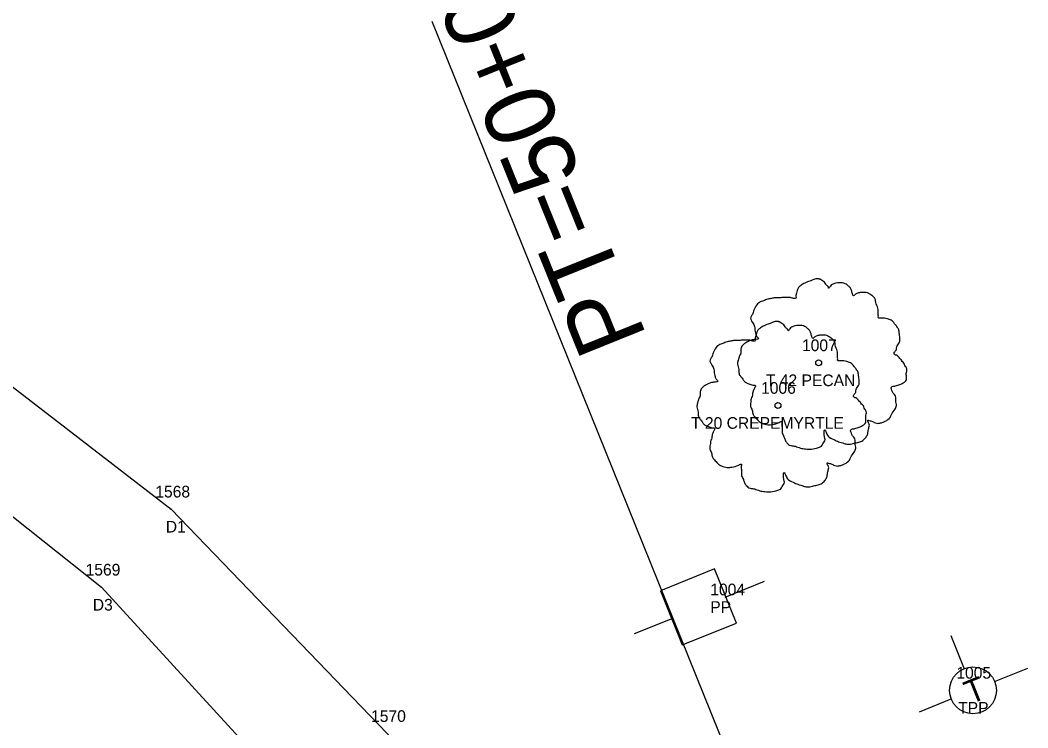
# Model space of a CAD drawing. Extents: x 1964982 to 1970452, y 1116335 to 1119906.
# Drawn here: x 1966698.6 to 1966784.8, y 1117479 to 1117539.6 of the extents above; entities that cross this region are included whole.
import ezdxf

# ---------------------------------------------------------------- set-up
doc = ezdxf.new("R2010")
doc.units = 0
for name, color, linetype in [('RD_EX_Driveway', 7, 'Continuous'), ('RD_EX_Driveway_txCode', 7, 'Continuous'), ('RD_EX_UT', 7, 'Continuous'), ('RD_EX_UT_txCode', 7, 'Continuous'), ('RD_EX_VEG', 7, 'Continuous'), ('RD_EX_VEG_txCode', 7, 'Continuous'), ('RD_HC_Data', 7, 'Continuous'), ('RD_SMD_Locator', 7, 'Continuous')]:
    doc.layers.add(name, color=color, linetype=linetype)

msp = doc.modelspace()

# ---------------------------------------------------------------- linework, layer by layer
at = {"layer": 'RD_EX_Driveway'}
for points in [[(1966578.028, 1117435.239), (1966571.581, 1117480.753), (1966567.97, 1117515.311), (1966576.556, 1117516.6), (1966582.112, 1117483.547), (1966603.624, 1117509.102), (1966634.749, 1117528.345), (1966662.085, 1117526.43), (1966689.524, 1117514.663), (1966711.523, 1117497.722), (1966730.008, 1117478.512), (1966744.031, 1117462.693), (1966734.107, 1117458.19)], [(1966589.3, 1117436.331), (1966587.977, 1117456.65), (1966594.083, 1117483.042), (1966609.697, 1117504.074), (1966638.325, 1117518.314), (1966661.317, 1117517.134), (1966685.434, 1117507.038), (1966705.558, 1117491.043), (1966722.871, 1117472.119), (1966734.107, 1117458.19)]]:
    msp.add_lwpolyline(points, dxfattribs=at)
at = {"layer": 'RD_EX_UT'}
for p, q in [((1966758.019, 1117492.607), (1966753.383, 1117490.734)), ((1966759.892, 1117487.971), (1966758.019, 1117492.607)), ((1966758.913, 1117490.204), (1966762.288, 1117491.568)), ((1966753.383, 1117490.734), (1966755.256, 1117486.098)), ((1966751.162, 1117487.073), (1966754.378, 1117488.373)), ((1966755.256, 1117486.098), (1966759.892, 1117487.971)), ((1966778.236, 1117486.915), (1966779.386, 1117484.069)), ((1966781.983, 1117482.978), (1966784.83, 1117484.128)), ((1966775.557, 1117480.382), (1966778.275, 1117481.48))]:
    msp.add_line(p, q, dxfattribs=at)
msp.add_circle((1966780.135, 1117482.215), 2, dxfattribs=at)
at = {"layer": 'RD_EX_VEG'}
for centre, radius in [((1966766.925, 1117510.253), 0.25), ((1966766.913, 1117510.234), 0.0001), ((1966763.446, 1117506.601), 0.25), ((1966763.434, 1117506.582), 0.0001)]:
    msp.add_circle(centre, radius, dxfattribs=at)
for points in [[(1966767.057, 1117517.42), (1966766.757, 1117517.445), (1966766.432, 1117517.345), (1966766.183, 1117517.245), (1966765.958, 1117517.17), (1966765.733, 1117517.07), (1966765.433, 1117516.896), (1966765.208, 1117516.696), (1966765.083, 1117516.446), (1966765.033, 1117516.221), (1966764.983, 1117515.946), (1966764.983, 1117515.771), (1966764.858, 1117515.746), (1966764.708, 1117515.771), (1966764.458, 1117515.846), (1966764.208, 1117515.846), (1966763.958, 1117515.846), (1966763.609, 1117515.821), (1966763.259, 1117515.821), (1966762.984, 1117515.771), (1966762.659, 1117515.721), (1966762.284, 1117515.596), (1966761.934, 1117515.471), (1966761.635, 1117515.221), (1966761.385, 1117514.747), (1966761.26, 1117514.397), (1966761.11, 1117514.147), (1966761.26, 1117513.697), (1966761.435, 1117513.347), (1966761.46, 1117513.147), (1966761.535, 1117512.722), (1966761.635, 1117512.498), (1966761.759, 1117512.298), (1966761.685, 1117512.273), (1966761.31, 1117512.223), (1966761.01, 1117512.123), (1966760.585, 1117511.898), (1966760.36, 1117511.673), (1966760.26, 1117511.348), (1966760.235, 1117510.998), (1966760.135, 1117510.798), (1966760.06, 1117510.523), (1966760.035, 1117510.448), (1966759.985, 1117510.124), (1966760.085, 1117509.674), (1966760.11, 1117509.324), (1966760.235, 1117509.099), (1966760.385, 1117508.924), (1966760.56, 1117508.674), (1966760.96, 1117508.449), (1966761.285, 1117508.349), (1966761.485, 1117508.324), (1966761.31, 1117507.825), (1966761.26, 1117507.475), (1966761.135, 1117507.075), (1966761.135, 1117507), (1966761.085, 1117506.525), (1966761.235, 1117506.2), (1966761.31, 1117505.825), (1966761.485, 1117505.601), (1966761.759, 1117505.301), (1966762.084, 1117505.076), (1966762.584, 1117504.951), (1966762.984, 1117504.976), (1966763.559, 1117505.151), (1966763.809, 1117505.226), (1966763.784, 1117505.051), (1966763.809, 1117504.676), (1966763.809, 1117504.251), (1966763.958, 1117503.926), (1966764.058, 1117503.651), (1966764.208, 1117503.401), (1966764.533, 1117503.177), (1966764.933, 1117503.102), (1966765.358, 1117502.952), (1966765.808, 1117502.877), (1966766.307, 1117502.852), (1966766.907, 1117503.002), (1966767.182, 1117503.127), (1966767.282, 1117503.302), (1966767.482, 1117503.676), (1966767.432, 1117503.901), (1966767.457, 1117504.501), (1966767.557, 1117504.326), (1966767.732, 1117503.976), (1966768.232, 1117503.676), (1966768.631, 1117503.501), (1966769.106, 1117503.351), (1966769.406, 1117503.277), (1966769.881, 1117503.351), (1966770.256, 1117503.426), (1966770.631, 1117503.551), (1966770.93, 1117503.826), (1966771.105, 1117504.101), (1966771.155, 1117504.376), (1966771.23, 1117504.751), (1966771.28, 1117504.926)], [(1966771.28, 1117504.926), (1966771.205, 1117505.101), (1966771.155, 1117505.351), (1966771.23, 1117505.326), (1966771.405, 1117505.276), (1966771.68, 1117505.151), (1966771.905, 1117505.076), (1966772.23, 1117505.101), (1966772.505, 1117505.201), (1966772.955, 1117505.476), (1966773.229, 1117505.95), (1966773.504, 1117506.35), (1966773.579, 1117506.675), (1966773.529, 1117506.9), (1966773.504, 1117507.4), (1966773.304, 1117507.65), (1966773.254, 1117507.775), (1966773.154, 1117508.174), (1966773.229, 1117508.224), (1966773.504, 1117508.274), (1966773.879, 1117508.399), (1966774.154, 1117508.524), (1966774.379, 1117508.699), (1966774.454, 1117508.924), (1966774.429, 1117509.324), (1966774.479, 1117509.724), (1966774.404, 1117509.874), (1966774.304, 1117510.024), (1966774.229, 1117510.224), (1966774.079, 1117510.373), (1966773.979, 1117510.523), (1966773.879, 1117510.623), (1966773.754, 1117510.773), (1966773.579, 1117510.898), (1966773.429, 1117510.948), (1966773.379, 1117511.098), (1966773.529, 1117511.298), (1966773.579, 1117511.398), (1966773.604, 1117511.623), (1966773.829, 1117511.973), (1966773.879, 1117512.373), (1966773.829, 1117512.797), (1966773.779, 1117513.072), (1966773.629, 1117513.347), (1966773.429, 1117513.597), (1966773.304, 1117513.772), (1966773.129, 1117513.897), (1966772.805, 1117514.022), (1966772.555, 1117514.072), (1966772.205, 1117514.072), (1966772.005, 1117514.122), (1966772.03, 1117514.172), (1966772.03, 1117514.322), (1966772.03, 1117514.597), (1966771.955, 1117515.046), (1966771.805, 1117515.546), (1966771.805, 1117515.571), (1966771.705, 1117515.821), (1966771.48, 1117516.021), (1966771.305, 1117516.121), (1966771.105, 1117516.246), (1966770.855, 1117516.271), (1966770.556, 1117516.271), (1966770.281, 1117516.221), (1966770.081, 1117516.121), (1966769.906, 1117515.996), (1966769.831, 1117516.146), (1966769.731, 1117516.446), (1966769.681, 1117516.596), (1966769.531, 1117516.771), (1966769.306, 1117516.971), (1966768.856, 1117517.095), (1966768.232, 1117517.021), (1966767.932, 1117516.821), (1966767.782, 1117516.646), (1966767.732, 1117516.771), (1966767.532, 1117516.971), (1966767.432, 1117517.145), (1966767.257, 1117517.27), (1966767.107, 1117517.37), (1966767.007, 1117517.42)], [(1966763.578, 1117513.768), (1966763.278, 1117513.793), (1966762.954, 1117513.693), (1966762.704, 1117513.594), (1966762.479, 1117513.519), (1966762.254, 1117513.419), (1966761.954, 1117513.244), (1966761.729, 1117513.044), (1966761.604, 1117512.794), (1966761.554, 1117512.569), (1966761.504, 1117512.294), (1966761.504, 1117512.119), (1966761.379, 1117512.094), (1966761.229, 1117512.119), (1966760.979, 1117512.194), (1966760.73, 1117512.194), (1966760.48, 1117512.194), (1966760.13, 1117512.169), (1966759.78, 1117512.169), (1966759.505, 1117512.119), (1966759.18, 1117512.069), (1966758.805, 1117511.944), (1966758.456, 1117511.819), (1966758.156, 1117511.569), (1966757.906, 1117511.095), (1966757.781, 1117510.745), (1966757.631, 1117510.495), (1966757.781, 1117510.045), (1966757.956, 1117509.695), (1966757.981, 1117509.495), (1966758.056, 1117509.071), (1966758.156, 1117508.846), (1966758.281, 1117508.646), (1966758.206, 1117508.621), (1966757.831, 1117508.571), (1966757.531, 1117508.471), (1966757.106, 1117508.246), (1966756.881, 1117508.021), (1966756.781, 1117507.696), (1966756.756, 1117507.346), (1966756.656, 1117507.146), (1966756.581, 1117506.871), (1966756.556, 1117506.796), (1966756.506, 1117506.472), (1966756.606, 1117506.022), (1966756.631, 1117505.672), (1966756.756, 1117505.447), (1966756.906, 1117505.272), (1966757.081, 1117505.022), (1966757.481, 1117504.797), (1966757.806, 1117504.697), (1966758.006, 1117504.672), (1966757.831, 1117504.173), (1966757.781, 1117503.823), (1966757.656, 1117503.423), (1966757.656, 1117503.348), (1966757.606, 1117502.873), (1966757.756, 1117502.548), (1966757.831, 1117502.174), (1966758.006, 1117501.949), (1966758.281, 1117501.649), (1966758.605, 1117501.424), (1966759.105, 1117501.299), (1966759.505, 1117501.324), (1966760.08, 1117501.499), (1966760.33, 1117501.574), (1966760.305, 1117501.399), (1966760.33, 1117501.024), (1966760.33, 1117500.599), (1966760.48, 1117500.274), (1966760.58, 1117499.999), (1966760.73, 1117499.75), (1966761.054, 1117499.525), (1966761.454, 1117499.45), (1966761.879, 1117499.3), (1966762.329, 1117499.225), (1966762.829, 1117499.2), (1966763.428, 1117499.35), (1966763.703, 1117499.475), (1966763.803, 1117499.65), (1966764.003, 1117500.024), (1966763.953, 1117500.249), (1966763.978, 1117500.849), (1966764.078, 1117500.674), (1966764.253, 1117500.324), (1966764.753, 1117500.024), (1966765.153, 1117499.85), (1966765.627, 1117499.7), (1966765.927, 1117499.625), (1966766.402, 1117499.7), (1966766.777, 1117499.775), (1966767.152, 1117499.9), (1966767.452, 1117500.174), (1966767.627, 1117500.449), (1966767.677, 1117500.724), (1966767.751, 1117501.099), (1966767.801, 1117501.274)], [(1966767.801, 1117501.274), (1966767.727, 1117501.449), (1966767.677, 1117501.699), (1966767.751, 1117501.674), (1966767.926, 1117501.624), (1966768.201, 1117501.499), (1966768.426, 1117501.424), (1966768.751, 1117501.449), (1966769.026, 1117501.549), (1966769.476, 1117501.824), (1966769.751, 1117502.298), (1966770.025, 1117502.698), (1966770.1, 1117503.023), (1966770.05, 1117503.248), (1966770.025, 1117503.748), (1966769.826, 1117503.998), (1966769.776, 1117504.123), (1966769.676, 1117504.522), (1966769.751, 1117504.572), (1966770.025, 1117504.622), (1966770.4, 1117504.747), (1966770.675, 1117504.872), (1966770.9, 1117505.047), (1966770.975, 1117505.272), (1966770.95, 1117505.672), (1966771, 1117506.072), (1966770.925, 1117506.222), (1966770.825, 1117506.372), (1966770.75, 1117506.572), (1966770.6, 1117506.721), (1966770.5, 1117506.871), (1966770.4, 1117506.971), (1966770.275, 1117507.121), (1966770.1, 1117507.246), (1966769.951, 1117507.296), (1966769.901, 1117507.446), (1966770.05, 1117507.646), (1966770.1, 1117507.746), (1966770.125, 1117507.971), (1966770.35, 1117508.321), (1966770.4, 1117508.721), (1966770.35, 1117509.145), (1966770.3, 1117509.42), (1966770.15, 1117509.695), (1966769.951, 1117509.945), (1966769.826, 1117510.12), (1966769.651, 1117510.245), (1966769.326, 1117510.37), (1966769.076, 1117510.42), (1966768.726, 1117510.42), (1966768.526, 1117510.47), (1966768.551, 1117510.52), (1966768.551, 1117510.67), (1966768.551, 1117510.945), (1966768.476, 1117511.394), (1966768.326, 1117511.894), (1966768.326, 1117511.919), (1966768.226, 1117512.169), (1966768.001, 1117512.369), (1966767.826, 1117512.469), (1966767.627, 1117512.594), (1966767.377, 1117512.619), (1966767.077, 1117512.619), (1966766.802, 1117512.569), (1966766.602, 1117512.469), (1966766.427, 1117512.344), (1966766.352, 1117512.494), (1966766.252, 1117512.794), (1966766.202, 1117512.944), (1966766.052, 1117513.119), (1966765.827, 1117513.319), (1966765.377, 1117513.444), (1966764.753, 1117513.369), (1966764.453, 1117513.169), (1966764.303, 1117512.994), (1966764.253, 1117513.119), (1966764.053, 1117513.319), (1966763.953, 1117513.494), (1966763.778, 1117513.619), (1966763.628, 1117513.718), (1966763.528, 1117513.768)]]:
    msp.add_spline(points, degree=3, dxfattribs=at)
at = {"layer": 'RD_HC_Data'}
msp.add_line((1966770.74, 1117448.117), (1966733.843, 1117539.46), dxfattribs=at)
at = {"layer": 'RD_SMD_Locator'}
for centre in [(1966711.523, 1117497.722), (1966711.523, 1117497.722), (1966705.558, 1117491.043), (1966705.558, 1117491.043)]:
    msp.add_circle(centre, 0.001, dxfattribs=at)

# ---------------------------------------------------------------- texts
at = {"layer": 'RD_EX_Driveway_txCode'}
for s, p in [('1568', (1966710.153, 1117498.722)), ('1568', (1966710.153, 1117498.722)), ('D1', (1966711.05, 1117495.722)), ('D1', (1966711.05, 1117495.722)), ('1569', (1966704.187, 1117492.043)), ('1569', (1966704.187, 1117492.043)), ('D3', (1966704.802, 1117489.043)), ('D3', (1966704.802, 1117489.043)), ('1570', (1966728.622, 1117479.512)), ('1570', (1966728.622, 1117479.512))]:
    msp.add_text(s, height=1, dxfattribs=at).set_placement(p)
at = {"layer": 'RD_EX_UT'}
msp.add_text('T', height=2, rotation=21.99584, dxfattribs=at).set_placement((1966779.906, 1117480.993))
at = {"layer": 'RD_EX_UT_txCode'}
for s, p in [('1004', (1966757.65, 1117490.348)), ('PP', (1966757.65, 1117488.848)), ('1005', (1966778.71, 1117483.215)), ('TPP', (1966778.867, 1117480.215))]:
    msp.add_text(s, height=1, dxfattribs=at).set_placement(p)
at = {"layer": 'RD_EX_VEG_txCode'}
for s, p in [('1007', (1966765.5, 1117511.253)), ('T 42 PECAN', (1966762.413, 1117508.253)), ('1006', (1966761.998, 1117507.601)), ('T 20 CREPEMYRTLE', (1966756.002, 1117504.601))]:
    msp.add_text(s, height=1, dxfattribs=at).set_placement(p)
at = {"layer": 'RD_HC_Data'}
msp.add_text('PT=50+00.00', height=6, rotation=111.99584, dxfattribs=at).set_placement((1966752.259, 1117512.485))

doc.saveas('drawing.dxf')
